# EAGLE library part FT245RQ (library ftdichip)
USB FIFO Controller 4th Generation USB Controller (USB <-> Parallel) - FIFO
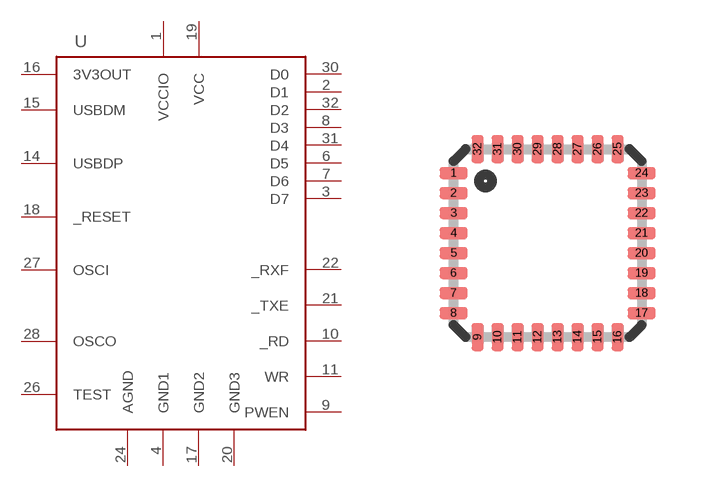
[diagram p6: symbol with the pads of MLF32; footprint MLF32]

Designator prefix -

## FT245RQ  [MLF32]
1  VCCIO  pwr
2  D1  in
3  D7  in
4  GND1  pwr
6  D5  in
7  D6  in
8  D3  in
9  PWEN
10  _RD
11  WR
14  USBDP
15  USBDM
16  3V3OUT  out
17  GND2  pwr
18  _RESET  in
19  VCC  pwr
20  GND3  pwr
21  _TXE
22  _RXF
24  AGND  pwr
26  TEST  in
27  OSCI  in
28  OSCO  out
30  D0  out
31  D4  out
32  D2  out

## Footprint MLF32 (pad centres in mm)
32M1-A Micro Lead Frame package (MLF)
smd 0.7 x 0.3: 1 -2.35,1.75; 2 -2.35,1.25; 3 -2.35,0.75; 4 -2.35,0.25; 5 -2.35,-0.25; 6 -2.35,-0.75; 7 -2.35,-1.25; 8 -2.35,-1.75; 17 2.35,-1.75; 18 2.35,-1.25; 19 2.35,-0.75; 20 2.35,-0.25; 21 2.35,0.25; 22 2.35,0.75; 23 2.35,1.25; 24 2.35,1.75
smd 0.3 x 0.7: 9 -1.75,-2.35; 10 -1.25,-2.35; 11 -0.75,-2.35; 12 -0.25,-2.35; 13 0.25,-2.35; 14 0.75,-2.35; 15 1.25,-2.35; 16 1.75,-2.35; 25 1.75,2.35; 26 1.25,2.35; 27 0.75,2.35; 28 0.25,2.35; 29 -0.25,2.35; 30 -0.75,2.35; 31 -1.25,2.35; 32 -1.75,2.35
